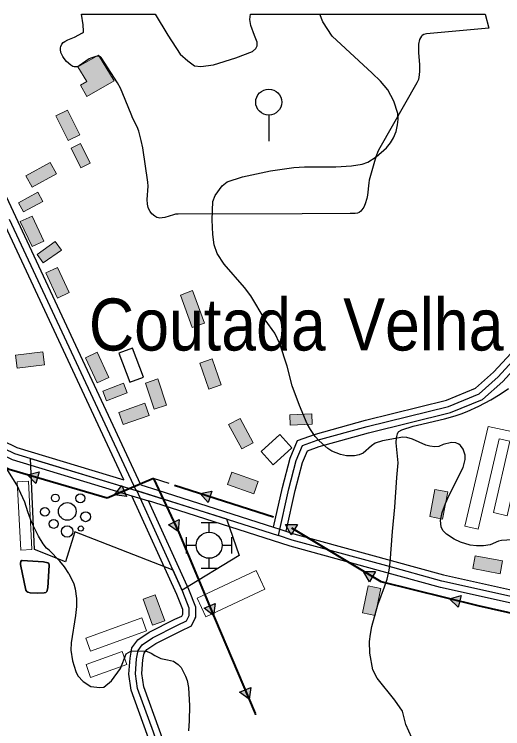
# Model space of a CAD drawing. Extents: x -64005 to -55000, y -89025 to -80000.
# Drawn here: x -57666 to -56916, y -81099 to -80000 of the extents above; entities that cross this region are included whole.
import ezdxf
from ezdxf.enums import TextEntityAlignment as Align

# ---------------------------------------------------------------- set-up
doc = ezdxf.new("R2010")
doc.units = 0
doc.header["$LTSCALE"] = 32
doc.linetypes.add('DOT_DASHED', pattern=[7.7, 5, -1.2, 0.3, -1.2])
doc.linetypes.add('LONG_DASHED', pattern=[7.5, 6, -1.5])
for name, color, linetype, lineweight in [('1', 7, 'Continuous', 25), ('16', 7, 'Continuous', 25), ('18', 7, 'Continuous', 25), ('24', 7, 'Continuous', 25), ('3', 7, 'Continuous', 25), ('32', 7, 'Continuous', 25), ('34', 7, 'Continuous', 25), ('39', 7, 'LONG_DASHED', 25), ('6', 7, 'Continuous', 25), ('7', 7, 'Continuous', 13), ('8', 7, 'Continuous', 25)]:
    doc.layers.add(name, color=color, linetype=linetype, lineweight=lineweight)
doc.layers.add('45', color=7, linetype='Continuous')

msp = doc.modelspace()

# ---------------------------------------------------------------- hatches: boundary and pattern name
at = {"layer": '18'}
for points in [[(-57633.4, -80721.5), (-57646.17, -80708.12), (-57628.2, -80703.74)], [(-57493.93, -80741.5), (-57512.28, -80739.18), (-57501.11, -80724.44)], [(-57368.54, -80750.8), (-57380.96, -80737.1), (-57362.88, -80733.19)], [(-57412.88, -80777.16), (-57414.46, -80795.59), (-57429.63, -80785)], [(-57240.78, -80800.63), (-57249.73, -80784.44), (-57231.23, -80784.79)], [(-57120.87, -80872.9), (-57129.82, -80856.71), (-57111.32, -80857.05)], [(-56984.2, -80911.9), (-56997.53, -80899.07), (-56979.75, -80893.95)], [(-57357.81, -80906.26), (-57360.13, -80924.61), (-57374.86, -80913.43)], [(-57303.21, -81035.14), (-57305.48, -81053.5), (-57320.25, -81042.37)]]:
    msp.add_hatch(color=256, dxfattribs=at).paths.add_polyline_path(points)
at = {"layer": '7'}
for points in [[(-57537.26, -80062.86), (-57568.76, -80080.52), (-57554.9, -80103.11), (-57564.81, -80109.06), (-57554.77, -80126.36), (-57512.82, -80102.16)], [(-57602.44, -80156.21), (-57583.43, -80194.22), (-57565.54, -80185.27), (-57584.55, -80147.26)], [(-57549.6, -80228.84), (-57564.81, -80198.44), (-57579.12, -80205.6), (-57563.91, -80236)], [(-57611.34, -80227.98), (-57648.65, -80248.33), (-57639.08, -80265.88), (-57601.77, -80245.53)], [(-57630.21, -80273.7), (-57660.06, -80289.98), (-57652.39, -80304.02), (-57622.54, -80287.74)], [(-57657.11, -80318.7), (-57639.16, -80357.23), (-57621.03, -80348.78), (-57638.98, -80310.25)], [(-57603.38, -80349.54), (-57631.09, -80369.24), (-57621.82, -80382.28), (-57594.11, -80362.58)], [(-57617.97, -80397.84), (-57600.01, -80436.36), (-57581.89, -80427.9), (-57599.85, -80389.38)], [(-57411.25, -80431.69), (-57393, -80481.92), (-57374.21, -80475.09), (-57392.46, -80424.86)], [(-57622.35, -80519.16), (-57664.55, -80524.17), (-57662.19, -80544.04), (-57619.99, -80539.03)], [(-57557.18, -80528.3), (-57539.23, -80566.83), (-57521.1, -80558.38), (-57539.05, -80519.85)], [(-57381.24, -80536.39), (-57367.44, -80576.59), (-57348.52, -80570.09), (-57362.32, -80529.89)], [(-57464.96, -80567.17), (-57451.53, -80607.49), (-57432.56, -80601.17), (-57445.99, -80560.85)], [(-57498.46, -80567.38), (-57530.26, -80579.41), (-57524.6, -80594.38), (-57492.8, -80582.35)], [(-57465.85, -80598.15), (-57505.97, -80612.19), (-57499.37, -80631.07), (-57459.25, -80617.03)], [(-57209.25, -80614.53), (-57243.23, -80615.89), (-57242.59, -80631.87), (-57208.61, -80630.51)], [(-57337.05, -80630.95), (-57316.92, -80668.38), (-57299.31, -80658.91), (-57319.44, -80621.48)], [(-57338.66, -80723.25), (-57298.56, -80737.31), (-57291.94, -80718.43), (-57332.04, -80704.37)], [(-57020.11, -80730.79), (-57028.21, -80772.51), (-57008.57, -80776.33), (-57000.47, -80734.61)], [(-56961.89, -80852.48), (-56920.12, -80860.32), (-56916.43, -80840.66), (-56958.2, -80832.82)], [(-57111.95, -80924.56), (-57103.07, -80883), (-57122.62, -80878.83), (-57131.5, -80920.39)], [(-57435.26, -80932.6), (-57449.79, -80892.67), (-57468.57, -80899.51), (-57454.06, -80939.43)]]:
    msp.add_hatch(color=256, dxfattribs=at).paths.add_polyline_path(points)

# ---------------------------------------------------------------- linework, layer by layer
at = {"layer": '1'}
for points in [[(-57136.49, -80677.64), (-57143.57, -80678.99), (-57155.74, -80679.03), (-57165.17, -80677.23), (-57178.6, -80672.07), (-57184.85, -80667.98), (-57198.15, -80655.98), (-57203.88, -80649.49), (-57211.44, -80638.79), (-57216.37, -80629.94), (-57228.42, -80601.47), (-57239.34, -80571.13), (-57246.9, -80540.89), (-57258.35, -80506.65), (-57266.19, -80490.32), (-57281.05, -80469.85), (-57303.08, -80432.83), (-57312.49, -80420.14), (-57343.93, -80384.2), (-57354.65, -80367.93), (-57359.53, -80354.64), (-57361.21, -80338.59), (-57362.3, -80316.06), (-57361.21, -80287.89), (-57357.92, -80278.84), (-57347.05, -80263.83), (-57339.4, -80257.52), (-57315.93, -80249.71), (-57272.97, -80240.95), (-57236.72, -80235.58), (-57220.73, -80234.56), (-57172.46, -80234.32), (-57148.36, -80233.03), (-57131.88, -80230.43), (-57123.41, -80227.24), (-57110.33, -80219.11), (-57094.45, -80205.28), (-57088.3, -80197.65), (-57083.69, -80189.71), (-57079.88, -80180.39), (-57077.4, -80169.95), (-57076.65, -80161.54), (-57076.91, -80152.59), (-57083.14, -80133.38), (-57092.71, -80116.35), (-57103.88, -80103.05), (-57116.65, -80090.28), (-57177.82, -80033.35), (-57192.18, -80011.53), (-57196.95, -80000)], [(-56901.47, -80808.46), (-56917.76, -80809.11), (-56922.24, -80810.35), (-56935.03, -80816.16), (-56945.56, -80817.69), (-56956.25, -80817.62), (-56965.99, -80816.26), (-56980.64, -80811.86), (-56990.34, -80807.31), (-57002.23, -80799.74), (-57007.83, -80793.81), (-57010.31, -80788.14), (-57011.63, -80778.25), (-57008.99, -80766.3), (-57004.05, -80752.29), (-56998.4, -80739.73), (-56976.55, -80697.01), (-56973.58, -80684.72), (-56973.72, -80678.26), (-56976.55, -80668.86), (-56980.69, -80663.14), (-56983.34, -80660.98), (-56987.89, -80658.96), (-56994.51, -80658.47), (-57007.7, -80661.43), (-57014.35, -80664.44), (-57020.21, -80665.05), (-57027.78, -80664.43), (-57034.29, -80662.48), (-57054.65, -80653.37), (-57063.16, -80650.9), (-57069.52, -80650.5), (-57100.85, -80656.05), (-57111.91, -80659.37), (-57117.8, -80663.55), (-57130.23, -80675.19), (-57136.49, -80677.64)], [(-57582.53, -80859.9), (-57589.13, -80850), (-57596.48, -80840.9), (-57612.67, -80823.93), (-57617.07, -80820.85), (-57622.2, -80814.17), (-57629.4, -80802.57), (-57639.22, -80782.22), (-57645.65, -80765.28), (-57650.08, -80750.29), (-57662.7, -80723.53), (-57678.76, -80697.72)], [(-57582.53, -80859.9), (-57574.96, -80876.13), (-57572.84, -80883.52), (-57570.57, -80898.62), (-57570.57, -80910.74), (-57572.19, -80924.76), (-57579.22, -80966.72), (-57579.5, -80977.89), (-57576.92, -80994.48), (-57571.87, -81010.99), (-57568.74, -81017.25), (-57560.82, -81026.17), (-57548.67, -81034.06), (-57535.02, -81035.5), (-57528.6, -81034.84), (-57517.05, -81025.06), (-57503.39, -81006.27), (-57494.57, -80983.77), (-57487.5, -80979.29), (-57464.57, -80979.16), (-57455.86, -80982.35), (-57450.47, -80986.2), (-57441.34, -80990.61), (-57430.81, -80992.88), (-57421.99, -80994.88), (-57418, -80997.44), (-57414.59, -81000), (-57410.23, -81004.45), (-57403.41, -81017.77), (-57400.91, -81024.58), (-57398.63, -81035.21), (-57397.02, -81063.76), (-57397.46, -81086.57), (-57398.87, -81102.15)]]:
    msp.add_lwpolyline(points, dxfattribs=at)
at = {"layer": '16'}
for p, q in [((-57379.5, -80781.65), (-57354.5, -80781.65)), ((-57367, -80796.65), (-57367, -80781.65)), ((-57402, -80829.15), (-57402, -80804.15)), ((-57332, -80829.15), (-57332, -80804.15)), ((-57402, -80816.65), (-57387, -80816.65)), ((-57347, -80816.65), (-57332, -80816.65)), ((-57367, -80851.65), (-57367, -80836.65)), ((-57379.5, -80851.65), (-57354.5, -80851.65))]:
    msp.add_line(p, q, dxfattribs=at)
for points in [[(-57488.78, -80565.78), (-57467.74, -80557.8), (-57484.58, -80513.38), (-57505.62, -80521.36)], [(-57656.94, -80846.13), (-57648.59, -80885.71), (-57646.95, -80887.9), (-57645.72, -80888.86), (-57642.02, -80889.68), (-57630.66, -80890.09), (-57620.39, -80889.95), (-57618.07, -80889.13), (-57616.56, -80887.49), (-57614.65, -80882.15), (-57612.73, -80847.37), (-57613.55, -80844.76), (-57614.78, -80843.53), (-57621.49, -80841.89), (-57654.2, -80839.83), (-57655.3, -80840.24), (-57656.26, -80841.48), (-57656.94, -80844.08)]]:
    msp.add_lwpolyline(points, close=True, dxfattribs=at)
msp.add_circle((-57367, -80816.65), 20, dxfattribs=at)
at = {"layer": '18'}
for p, q in [((-57559.8, -80733.41), (-57630.8, -80712.62)), ((-57452.61, -80714.07), (-57421.25, -80781.08)), ((-57295.28, -80764.63), (-57365.71, -80742)), ((-57172.64, -80830.9), (-57236, -80792.71)), ((-57395.02, -80841.65), (-57366.34, -80909.84)), ((-57340.61, -80970.65), (-57311.73, -81038.75))]:
    msp.add_line(p, q, dxfattribs=at)
at = {"layer": '18', "linetype": 'DOT_DASHED', "lineweight": 40}
for points in [[(-56806.36, -80942.81), (-56953.76, -80909.92), (-57102.87, -80872.95), (-57268.09, -80773.37), (-57452.61, -80714.07), (-57523.68, -80743.98), (-57674.42, -80699.85), (-57727.93, -80674.98), (-57838.73, -80585.07), (-57997.82, -80458.17), (-58069.39, -80403.64), (-58117.07, -80374.59), (-58411.27, -80212.46), (-58533.19, -80215.56), (-58561.43, -80162.65)], [(-57452.61, -80714.07), (-57413.78, -80797.05), (-57358.72, -80927.95), (-57172.16, -81367.87), (-57046.34, -81465.7), (-56967.93, -81530.06), (-56872.99, -81606.79), (-56781.18, -81782.9), (-56733.96, -81876.25), (-56658.11, -82020.58), (-56589.53, -82041.38), (-56283.61, -81969.09), (-56306.89, -81859.59)]]:
    msp.add_lwpolyline(points, dxfattribs=at)
at = {"layer": '18'}
for points in [[(-57633.4, -80721.5), (-57646.17, -80708.12), (-57628.2, -80703.74)], [(-57493.93, -80741.5), (-57512.28, -80739.18), (-57501.11, -80724.44)], [(-57368.54, -80750.8), (-57380.96, -80737.1), (-57362.88, -80733.19)], [(-57412.88, -80777.16), (-57414.46, -80795.59), (-57429.63, -80785)], [(-57240.78, -80800.63), (-57249.73, -80784.44), (-57231.23, -80784.79)], [(-57120.87, -80872.9), (-57129.82, -80856.71), (-57111.32, -80857.05)], [(-56984.2, -80911.9), (-56997.53, -80899.07), (-56979.75, -80893.95)], [(-57357.81, -80906.26), (-57360.13, -80924.61), (-57374.86, -80913.43)], [(-57303.21, -81035.14), (-57305.48, -81053.5), (-57320.25, -81042.37)]]:
    msp.add_lwpolyline(points, close=True, dxfattribs=at)
for points in [[(-57428.56, -80721.8), (-57452.61, -80714.07), (-57497.52, -80732.97)], [(-57046.06, -80887.04), (-57102.87, -80872.95), (-57116.1, -80864.98)], [(-56909.93, -80919.7), (-56953.76, -80909.92), (-56981.98, -80902.92)]]:
    msp.add_lwpolyline(points, dxfattribs=at)
for centre in [(-57404.76, -80729.45), (-57535.81, -80740.43), (-57271.48, -80772.28), (-57404.71, -80818.6), (-57151.23, -80843.8), (-57021.79, -80893.05), (-57350.37, -80947.63), (-57295.71, -81076.52)]:
    msp.add_circle(centre, 0.5, dxfattribs=at)
at = {"layer": '24'}
for points in [[(-56942.82, -80000), (-56937.12, -80021.27), (-57032.88, -80030.2), (-57037.06, -80031.15), (-57039.67, -80032.64), (-57040.76, -80033.61), (-57042.54, -80035.95), (-57043.84, -80038.8), (-57045.23, -80045.77), (-57045.44, -80049.78), (-57045.21, -80058.58), (-57043.85, -80077.75), (-57043.7, -80087.22), (-57044.12, -80093.18), (-57045.5, -80100.02), (-57047.77, -80105.38), (-57105.03, -80205.27), (-57107.38, -80209.84), (-57111.14, -80219.39), (-57121.08, -80255.17), (-57121.75, -80259.16), (-57123.76, -80278.03), (-57124.7, -80283.39), (-57127.08, -80291.33), (-57129.57, -80296.51), (-57134.03, -80302.83), (-57136.6, -80304.97), (-57138.89, -80305.91), (-57142.58, -80306.42), (-57150.18, -80306.23), (-57224.13, -80307.09), (-57414.52, -80307.11), (-57418.83, -80307.54), (-57421.71, -80308.22), (-57435.18, -80312.49), (-57439.02, -80313.19), (-57442.83, -80313.26), (-57444.73, -80312.99), (-57447.24, -80312.25), (-57450.37, -80310.63), (-57454.88, -80306.67), (-57457.69, -80303.13), (-57459.74, -80299.53), (-57460.73, -80297.09), (-57461.95, -80292.14), (-57462.33, -80284.58), (-57460.69, -80264.2), (-57461.18, -80257.93), (-57469.03, -80205.46), (-57471.3, -80193.89), (-57474.92, -80179.54), (-57477.53, -80172.9), (-57484.08, -80160.21), (-57486.95, -80153.62), (-57499.4, -80122.34), (-57503.39, -80113.63), (-57507.91, -80105.21), (-57532.66, -80066.51), (-57533.81, -80065.29), (-57534.78, -80064.77), (-57537.07, -80064.35), (-57541.06, -80064.86), (-57548.81, -80067.36), (-57551.4, -80068.48), (-57566.58, -80079.18), (-57570.01, -80080.62), (-57571.75, -80080.97), (-57574.24, -80080.85), (-57576.56, -80080.11), (-57579.4, -80078.42), (-57586.11, -80072.39), (-57589.65, -80068.09), (-57591.63, -80065.11), (-57594.7, -80058.86), (-57595.57, -80054.26), (-57595.45, -80051.76), (-57594.92, -80049.27), (-57593.36, -80045.86), (-57591.3, -80043.56), (-57588.97, -80041.86), (-57584.1, -80039.19), (-57574.05, -80035.02), (-57561.4, -80028.72), (-57560.3, -80027.56), (-57559.86, -80025.7), (-57560.71, -80016.15)], [(-57560.71, -80016.15), (-57563.37, -80000), (-57449.99, -80000)], [(-57449.99, -80000), (-57430.3, -80032.04), (-57411.52, -80061.3), (-57400.01, -80071.53), (-57389.7, -80079.2), (-57380.01, -80080.06), (-57360.32, -80077.5), (-57326.08, -80066.7), (-57300.33, -80057.32), (-57295.48, -80052.49), (-57293.06, -80048.23), (-57293.36, -80042.83), (-57297.3, -80032.32), (-57303.05, -80017.26), (-57304.57, -80008.17), (-57303.45, -79999.95), (-56942.82, -80000)], [(-57108.75, -81020.97), (-57115.6, -81007.95), (-57120.26, -80982.48), (-57120.53, -80964.4), (-57119.16, -80953.45), (-57117.24, -80941.39), (-57107.67, -80908.39), (-57097.81, -80880.72), (-57093.43, -80868.95), (-57090.68, -80855.12), (-57088.77, -80843.07), (-57085.2, -80795.56), (-57081.92, -80757.76), (-57078.63, -80712.15), (-57076.72, -80689.69), (-57078.51, -80669.4), (-57079.66, -80659.13), (-57079.32, -80651.43), (-57077.86, -80645.01), (-57076.7, -80642.83), (-57075.35, -80641.42), (-57070.9, -80638.88), (-57053.71, -80633.46), (-57047.01, -80631.67), (-57005.44, -80622.24), (-56988.95, -80617.72), (-56979.72, -80614.46), (-56970.65, -80610.75), (-56952.8, -80602.48), (-56934.42, -80592.78), (-56920.14, -80584.19), (-56907.23, -80575.58)], [(-57340.6, -80776.14), (-57320.82, -80832.52), (-57408.47, -80885.65), (-57422.55, -80854.78), (-57573.26, -80795.68), (-57576, -80804.31), (-57587.5, -80841.84), (-57635.14, -80823.07), (-57641.64, -80682.95)], [(-57641.64, -80682.95), (-57479.38, -80732.15), (-57340.6, -80776.14)], [(-56910.81, -81391.28), (-56917.38, -81381.42), (-56930.25, -81361.97), (-56943.94, -81334.58), (-56966.39, -81296.23), (-56982.82, -81265.84), (-57003.08, -81226.39), (-57018.41, -81199), (-57027.71, -81176.26), (-57037.57, -81154.35), (-57051.26, -81123.12), (-57064.95, -81092.17), (-57069.88, -81071.9), (-57081.93, -81054.92), (-57108.75, -81020.97)]]:
    msp.add_lwpolyline(points, dxfattribs=at)
at = {"layer": '3'}
msp.add_lwpolyline([(-57656.94, -80846.13), (-57656.94, -80844.08), (-57656.26, -80841.48), (-57655.3, -80840.24), (-57654.2, -80839.83), (-57621.49, -80841.89), (-57614.78, -80843.53), (-57613.55, -80844.76), (-57612.73, -80847.37), (-57614.65, -80882.15), (-57616.56, -80887.49), (-57618.07, -80889.13), (-57620.39, -80889.95), (-57630.66, -80890.09), (-57642.02, -80889.68), (-57645.72, -80888.86), (-57646.95, -80887.9), (-57648.59, -80885.71)], close=True, dxfattribs=at)
at = {"layer": '32'}
msp.add_line((-57275.44, -80155.04), (-57275.44, -80195.04), dxfattribs=at)
msp.add_circle((-57275.44, -80135.04), 20, dxfattribs=at)
at = {"layer": '34'}
for centre, radius in [((-57564.93, -80744.37), 6.8), ((-57603.33, -80743.99), 6), ((-57619.34, -80765.2), 6.8), ((-57584.95, -80764.51), 13.6), ((-57556.82, -80772.7), 7.6), ((-57605.83, -80783.75), 6.8), ((-57585.15, -80795.26), 8.8), ((-57564.25, -80790.88), 4)]:
    msp.add_circle(centre, radius, dxfattribs=at)
at = {"layer": '39', "linetype": 'Continuous'}
msp.add_line((-57479.38, -80732.15), (-57673.63, -80315.44), dxfattribs=at)
at = {"layer": '39', "linetype": 'Continuous', "lineweight": 35}
msp.add_line((-57479.38, -80732.15), (-57478.35, -80732.46), dxfattribs=at)
at = {"layer": '39'}
for points in [[(-57260.64, -80801.8), (-57244.68, -80729.91), (-57233.3, -80686.02), (-57223.56, -80663.27), (-57200.82, -80655.14), (-57124.47, -80634), (-56999.37, -80603.1), (-56952.26, -80583.58), (-56923.01, -80557.58), (-56871.03, -80500.69), (-56830.42, -80434.04), (-56804.01, -80366.11)], [(-57349.26, -81387.51), (-57400.74, -81247.96), (-57452.73, -81104.11), (-57477, -81036.99), (-57480.25, -81014.23), (-57478.62, -80991.48), (-57476.18, -80978.48), (-57469.69, -80969.53), (-57454.25, -80958.96), (-57415.39, -80939.49), (-57401.58, -80932.98), (-57397.52, -80924.85), (-57397.52, -80913.47), (-57407.27, -80888.28), (-57478.35, -80732.46)]]:
    msp.add_lwpolyline(points, dxfattribs=at)
at = {"layer": '39', "linetype": 'Continuous'}
for points in [[(-57759.65, -80615.54), (-57713.22, -80652.78), (-57666.11, -80675.53), (-57479.38, -80732.15)], [(-57478.35, -80732.46), (-57448.96, -80741.37), (-57260.64, -80801.8)], [(-56608.21, -80961.04), (-57009.4, -80871.71), (-57094.18, -80848.45), (-57239.56, -80808.57), (-57260.64, -80801.8)]]:
    msp.add_lwpolyline(points, dxfattribs=at)
at = {"layer": '6'}
msp.add_line((-57497.9, -80716.08), (-57679.84, -80325.79), dxfattribs=at)
for points in [[(-57472.2, -80723.87), (-57764.42, -80096.99), (-57809.78, -80000)], [(-57981.29, -80452.58), (-57799.91, -80596.07), (-57718.59, -80661.29), (-57669.76, -80684.87), (-57485.58, -80740.71), (-57460.07, -80748.45)], [(-57755.05, -80606.4), (-57707.85, -80644.27), (-57662.46, -80666.19), (-57497.9, -80716.08)], [(-57472.2, -80723.87), (-57445.98, -80731.82), (-57268.03, -80788.93), (-57258.5, -80792)], [(-56610.27, -80970.82), (-57011.81, -80881.42), (-57106.82, -80855.35), (-57242.41, -80818.16), (-57451.94, -80750.92), (-57460.07, -80748.45)], [(-57258.5, -80792), (-57236.7, -80798.98), (-57007, -80862), (-56606.15, -80951.26)]]:
    msp.add_lwpolyline(points, dxfattribs=at)
at = {"layer": '7'}
for points in [[(-57537.26, -80062.86), (-57568.76, -80080.52), (-57554.9, -80103.11), (-57564.81, -80109.06), (-57554.77, -80126.36), (-57512.82, -80102.16)], [(-57602.44, -80156.21), (-57583.43, -80194.22), (-57565.54, -80185.27), (-57584.55, -80147.26)], [(-57549.6, -80228.84), (-57564.81, -80198.44), (-57579.12, -80205.6), (-57563.91, -80236)], [(-57611.34, -80227.98), (-57648.65, -80248.33), (-57639.08, -80265.88), (-57601.77, -80245.53)], [(-57630.21, -80273.7), (-57660.06, -80289.98), (-57652.39, -80304.02), (-57622.54, -80287.74)], [(-57657.11, -80318.7), (-57639.16, -80357.23), (-57621.03, -80348.78), (-57638.98, -80310.25)], [(-57603.38, -80349.54), (-57631.09, -80369.24), (-57621.82, -80382.28), (-57594.11, -80362.58)], [(-57617.97, -80397.84), (-57600.01, -80436.36), (-57581.89, -80427.9), (-57599.85, -80389.38)], [(-57411.25, -80431.69), (-57393, -80481.92), (-57374.21, -80475.09), (-57392.46, -80424.86)], [(-57622.35, -80519.16), (-57664.55, -80524.17), (-57662.19, -80544.04), (-57619.99, -80539.03)], [(-57557.18, -80528.3), (-57539.23, -80566.83), (-57521.1, -80558.38), (-57539.05, -80519.85)], [(-57381.24, -80536.39), (-57367.44, -80576.59), (-57348.52, -80570.09), (-57362.32, -80529.89)], [(-57464.96, -80567.17), (-57451.53, -80607.49), (-57432.56, -80601.17), (-57445.99, -80560.85)], [(-57498.46, -80567.38), (-57530.26, -80579.41), (-57524.6, -80594.38), (-57492.8, -80582.35)], [(-57465.85, -80598.15), (-57505.97, -80612.19), (-57499.37, -80631.07), (-57459.25, -80617.03)], [(-57209.25, -80614.53), (-57243.23, -80615.89), (-57242.59, -80631.87), (-57208.61, -80630.51)], [(-57337.05, -80630.95), (-57316.92, -80668.38), (-57299.31, -80658.91), (-57319.44, -80621.48)], [(-56974.01, -80787.2), (-56938.39, -80634.05), (-56881, -80646.26), (-56908.92, -80771.07), (-56929.89, -80766.38), (-56905.29, -80656.42), (-56921.48, -80652.98), (-56953.8, -80791.9)], [(-57239.79, -80666.71), (-57268.67, -80692.88), (-57287.08, -80672.55), (-57258.21, -80646.39)], [(-57338.66, -80723.25), (-57298.56, -80737.31), (-57291.94, -80718.43), (-57332.04, -80704.37)], [(-57661.91, -80719.03), (-57644.65, -80718.13), (-57639.19, -80823.22), (-57656.45, -80824.12)], [(-57020.11, -80730.79), (-57028.21, -80772.51), (-57008.57, -80776.33), (-57000.47, -80734.61)], [(-56961.89, -80852.48), (-56920.12, -80860.32), (-56916.43, -80840.66), (-56958.2, -80832.82)], [(-57294.93, -80855.36), (-57281.57, -80883.89), (-57372.09, -80926.56), (-57385.45, -80898.03)], [(-57111.95, -80924.56), (-57103.07, -80883), (-57122.62, -80878.83), (-57131.5, -80920.39)], [(-57435.26, -80932.6), (-57449.79, -80892.67), (-57468.57, -80899.51), (-57454.06, -80939.43)], [(-57556.48, -80959.34), (-57470.24, -80927.99), (-57463.18, -80948.03), (-57549.42, -80979.38)], [(-57556.21, -80999.77), (-57500.5, -80980.13), (-57493.44, -81000.17), (-57549.15, -81019.81)]]:
    msp.add_lwpolyline(points, close=True, dxfattribs=at)
at = {"layer": '8', "linetype": 'LONG_DASHED'}
for points in [[(-57268.03, -80788.93), (-57254.4, -80727.57), (-57242.79, -80682.78), (-57231.04, -80655.32), (-57203.84, -80645.6), (-57127, -80624.32), (-57002.5, -80593.57), (-56957.64, -80574.99), (-56930.04, -80550.45), (-56879.07, -80494.66), (-56839.75, -80430.14), (-56813.71, -80363.47)], [(-57407.52, -80920.62), (-57407.52, -80915.34), (-57416.49, -80892.16), (-57485.58, -80740.71)], [(-57486.8, -80980.9), (-57485.59, -80974.43), (-57476.77, -80962.26), (-57459.34, -80950.32), (-57419.76, -80930.49), (-57408.98, -80925.42), (-57407.52, -80922.49), (-57407.52, -80920.62)], [(-57358.66, -81390.92), (-57410.13, -81251.39), (-57462.13, -81107.51), (-57486.75, -81039.42), (-57490.3, -81014.58), (-57488.55, -80990.2), (-57486.8, -80980.9)]]:
    msp.add_lwpolyline(points, dxfattribs=at)
at = {"layer": '8'}
for points in [[(-57248.9, -80795.07), (-57234.96, -80732.24), (-57223.81, -80689.26), (-57216.08, -80671.22), (-57197.8, -80664.68), (-57121.94, -80643.68), (-56996.24, -80612.63), (-56946.88, -80592.17), (-56915.98, -80564.71), (-56862.99, -80506.72), (-56821.09, -80437.94), (-56794.31, -80368.73)], [(-57388.85, -80929.87), (-57387.52, -80927.21), (-57387.52, -80911.6), (-57398.05, -80884.4), (-57460.07, -80748.45)], [(-57467.62, -80987.07), (-57466.77, -80982.52), (-57462.61, -80976.8), (-57449.16, -80967.6), (-57411.02, -80948.49), (-57394.18, -80940.55), (-57388.85, -80929.87)], [(-57339.86, -81384.1), (-57391.35, -81244.52), (-57443.33, -81100.71), (-57467.25, -81034.56), (-57470.2, -81013.88), (-57468.69, -80992.76), (-57467.62, -80987.07)]]:
    msp.add_lwpolyline(points, dxfattribs=at)

# ---------------------------------------------------------------- texts
at = {"layer": '45', "width": 0.9}
msp.add_text('Coutada Velha', height=80, rotation=0.007, dxfattribs=at).set_placement((-57233.27, -80517.05), align=Align.CENTER)

doc.saveas('drawing.dxf')
